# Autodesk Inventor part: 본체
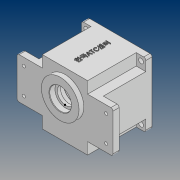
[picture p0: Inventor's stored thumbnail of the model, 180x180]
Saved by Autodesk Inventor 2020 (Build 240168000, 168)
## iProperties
Created: 2020-07
Part Number: 본체
Material: 일반
Document SubType Name: Modeling
Designer: PC312-
Density: 1 g/cm^3
Appearance: 기본값
Author: PC312-
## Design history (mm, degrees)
sketch "스케치1"
  geometry: L1 (33, -47)-(-33, -47); L2 (-33, -47)-(-33, 47); L3 (-33, 47)-(33, 47); L4 (33, 47)-(33, -47); L5 (33, -47)-(-33, 47); L6 (-33, -47)-(33, 47); L7 (70, 30)-(-70, 30); L8 (-70, 30)-(-70, -30); L9 (-70, -30)-(70, -30); L10 (70, -30)-(70, 30); L11 (70, 30)-(-70, -30); L12 (-70, 30)-(70, -30); 5 further points
  constraints: 24 end point, 4 midpoint, 4 parallel, 2 horizontal, 2 perpendicular
  dimensions: "d0" = 66 distance of L2.end L3.end; "d1" = 94 distance of L1.end L2.end; "d2" = 140 distance of L9.end L8.end; "d3" = 60 distance of L8.end L7.end
extrude "돌출2" new body sketch "스케치1" distance "d6" = 71; taper "d7" = 0 deg
extrude "돌출3" join sketch "스케치1" distance "d8" = 80; taper "d9" = 0 deg
sketch "스케치3"
  geometry: C1 r 27.5 at (0, 11); 1 further point
  constraints: 1 centre point, 1 vertical alignment
  dimensions: "d13" = 55 diameter of C1; "d14" = 11 distance of point (0, 0) C1.centre
extrude "돌출4" join sketch "스케치3" distance "d15" = 7; taper "d16" = 0 deg
sketch "스케치4"
  geometry: C1 r 27.5 at (0, 0) reference; C2 r 16 at (0, 0); 1 further point
  constraints: 1 centre point, 1 coincident
  dimensions: "d17" = 32 diameter of C2
extrude "돌출5" cut sketch "스케치4" distance "d18" = 8.3; taper "d19" = 0 deg
sketch "스케치5"
  geometry: C1 r 27.5 at (0, 0) reference; C2 r 12.5 at (0, 0); 1 further point
  constraints: 1 centre point, 1 coincident
  dimensions: "d20" = 25 diameter of C2
extrude "돌출6" cut sketch "스케치5" distance "d21" = 9; taper "d22" = 0 deg
node "작업 평면3"
sketch "스케치7"
  geometry: L1 (-47, -47)-(47, -47); L2 (47, -47)-(47, 47); L3 (47, 47)-(-47, 47); L4 (-47, 47)-(-47, -47); L5 (-47, -47)-(47, 47); L6 (47, -47)-(-47, 47); 1 further point
  constraints: 12 end point, 2 midpoint, 2 parallel, 1 horizontal, 1 perpendicular
  dimensions: "d27" = 94 distance of L3.end L2.end; "d28" = 94 distance of L2.end L1.end
extrude "돌출7" join sketch "스케치7" distance "d29" = 9; taper "d30" = 0 deg
sketch "스케치9"
  geometry: C1 r 43 at (0, 0); 1 further point
  constraints: 1 centre point, 1 coincident
  dimensions: "d32" = 86 diameter of C1
extrude "돌출8" cut sketch "스케치9" distance "d33" = 9; taper "d34" = 0 deg
sketch "스케치10"
  geometry: C1 r 40 at (0, 0); 1 further point
  constraints: 1 centre point, 1 coincident
  dimensions: "d35" = 80 diameter of C1
extrude "돌출9" cut sketch "스케치10" distance "d36" = 62; taper "d37" = 0 deg
sketch "스케치14"
  geometry: L1 (80, 80)-(-14, 80) reference; L2 (66, 0)-(0, 0) reference; 3 further points
  constraints: 1 midpoint, 1 vertical alignment, 1 other
  dimensions: "d54" = 40 distance from line of L1 point (33, 40)
feature "엠보싱1" sketch "스케치14" dims "d55" = 1, "d56" = 0
sketch "스케치15"
  geometry: C1 r 40 at (0, 0) reference; C2 r 43 at (0, 0) reference; A1 r 36 centre (0, 0) between (35.778, 3.994) and (35.778, -3.994); A2 r 4 centre (36, 0) between (35.778, 3.994) and (35.778, -3.994); A3 r 4 centre (-36, 0) between (-35.778, -3.994) and (-35.778, 3.994); 1 further point
  constraints: 9 point on circle, 3 centre point, 2 horizontal alignment, 1 coincident, 1 tangent
  dimensions: "d57" = 72 diameter of A1; "d58" = 8 diameter of A2; "d59" = 8 diameter of A3
sketch "스케치17"
  geometry: A1 r 21 centre (0, 11) between (8.978, -7.984) and (-8.978, -7.984); A2 r 15 centre (0, -20) between (-8.978, -7.984) and (8.978, -7.984); 1 further point
  constraints: 4 point on circle, 3 vertical alignment, 2 centre point
  dimensions: "d60" = 42 diameter of A1; "d61" = 11 distance of point (0, 0) A1.centre; "d62" = 30 diameter of A2; "d63" = 20 distance of A2.centre point (0, 0)
extrude "돌출15" join sketch "스케치17" distance "d64" = 7; taper "d65" = 0 deg
sketch "스케치18"
  geometry: C1 r 11 at (0, -20); 1 further point
  constraints: 1 centre point, 1 vertical alignment
  dimensions: "d66" = 22 diameter of C1; "d67" = 20 distance of C1.centre point (0, 0)
extrude "돌출16" cut sketch "스케치18" distance "d68" = 7; taper "d69" = 0 deg
sketch "스케치19"
  geometry: C1 r 11 at (0, 0) reference; C2 r 9.5 at (0, 0); 1 further point
  constraints: 1 centre point, 1 coincident
  dimensions: "d70" = 19 diameter of C2
extrude "돌출17" cut sketch "스케치19" distance "d71" = 3; taper "d72" = 0 deg
sketch "스케치20"
  geometry: C1 r 17.5 at (0, 11); A1 r 21 centre (0, 11) between (8.978, -7.984) and (-8.978, -7.984) reference; 1 further point
  constraints: 1 centre point, 1 coincident
  dimensions: "d73" = 35 diameter of C1
extrude "돌출18" cut sketch "스케치20" distance "d74" = 10; taper "d75" = 0 deg
fillet "모깎기1" dims "d76" = 3
chamfer "모따기1" distance "d77" = 1; stored, may be unused: second distance "d78" = 2, angle "d79" = 45 deg
chamfer "모따기2" distance "d80" = 1; stored, may be unused: second distance "d81" = 2, angle "d82" = 45 deg
chamfer "모따기3" distance "d83" = 1; stored, may be unused: second distance "d84" = 2, angle "d85" = 45 deg
chamfer "모따기4" distance "d86" = 0.8; stored, may be unused: second distance "d87" = 2, angle "d88" = 30 deg
fillet "모깎기2" dims "d89" = 3
sketch "스케치21"
  geometry: 1 further point
sketch "스케치22"
  geometry: 1 further point
sketch "스케치23"
  geometry: L1 (47, 30)-(47, 44) reference; L2 (44, 47)-(33, 47) reference; 2 further points
  dimensions: "d90" = 7 distance from line of L1 point (40, 40); "d91" = 7 distance from line of point (40, 40) L2
hole "구멍1" sketch "스케치23" at (40, 40) diameter "d92" = 7; stored, may be unused: countersink angle "d96" = 90 deg, drill point angle "d98" = 118 deg; dims "d93" = 6, "d94" = 4, "d95" = 2, "d97" = 8
sketch "스케치24"
  geometry: L1 (-44, -47)-(-33, -47) reference; L2 (-47, -30)-(-47, -44) reference; 2 further points
  dimensions: "d105" = 7 distance from line of L1 point (-40, -40); "d106" = 7 distance from line of L2 point (-40, -40)
hole "구멍2" sketch "스케치24" at (-40, -40) diameter "d107" = 7; stored, may be unused: countersink angle "d111" = 90 deg, drill point angle "d113" = 118 deg; dims "d108" = 6, "d109" = 4, "d110" = 2, "d112" = 8
sketch "스케치26"
  geometry: L1 (-23, 71)-(-23, 80) reference; L2 (-23, 71)-(-23, 0); L3 (0, 0)-(-37, 0) reference; L4 (-23, 71)-(0, 71) reference; L5 (-23, 71)-(0, 71); L6 (0, 0)-(0, 71) reference; L7 (0, 71)-(0, 0); L8 (0, 0)-(-23, 0); 1 further point
  constraints: 8 end point, 2 horizontal, 2 vertical, 1 point on line
extrude "돌출19" cut sketch "스케치26" extent not by distance; stored distance "d115" = 14; taper "d116" = 0 deg
sketch "스케치27"
  geometry: L1 (0, 0)-(37, 0) reference; L2 (23, 71)-(23, 0); L3 (23, 0)-(0, 0); L4 (23, 71)-(0, 71) reference; L5 (0, 71)-(23, 71); L6 (0, 0)-(0, 71) reference; L7 (0, 0)-(0, 71); 1 further point
  constraints: 8 end point, 2 horizontal, 2 vertical, 1 point on line
extrude "돌출20" cut sketch "스케치27" extent not by distance; stored distance "d117" = 0; taper "d118" = 0 deg
sketch "스케치28"
  geometry: L1 (33, 30)-(47, 30) reference; L2 (33, 30)-(70, 30); L3 (70, 30)-(70, -30); L4 (33, -47)-(33, -30) reference; L5 (33, -30)-(70, -30); L6 (47, -30)-(47, 30) reference; 2 further points
  constraints: 6 end point, 2 horizontal, 1 vertical
  dimensions: "d119" = 23 distance between parallel lines of L3 L6
extrude "돌출21" join sketch "스케치28" distance "d120" = 9; taper "d121" = 0 deg
fillet "모깎기3" dims "d122" = 3
sketch "스케치30"
  geometry: L1 (-70, 27)-(-70, -27) reference; L2 (-47, 30)-(-67, 30) reference; 2 further points
  dimensions: "d123" = 10 distance from line of L1 point (-60, 19); "d124" = 11 distance from line of point (-60, 19) L2
hole "구멍3" sketch "스케치30" at (-60, 19) diameter "d125" = 4.5; stored, may be unused: countersink angle "d129" = 90 deg, drill point angle "d131" = 0 deg; dims "d126" = 6, "d127" = 10, "d128" = 5, "d130" = 13
node "솔리드2"
pattern_linear "직사각형 패턴1" dims "d101" = 80
pattern_linear "직사각형 패턴2" dims "d104" = 80
mirror "미러1"
pattern_linear "직사각형 패턴3" dims "d134" = 120
pattern_linear "직사각형 패턴5" dims "d140" = 38
feature "A9D066F2-1C7D-4E18-AEED-F7BC21143FA4" dims "d92" = 7, "d93" = 6, "d94" = 4, "d95" = 2, "d96" = 90 deg, "d97" = 8, "d98" = 118 deg
